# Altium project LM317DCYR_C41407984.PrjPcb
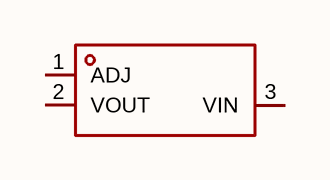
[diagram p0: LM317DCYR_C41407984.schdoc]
1 sheet, 1 parts. Net scope: global (net labels, ports and power ports of the same name join across sheets).

## Sheet LM317DCYR_C41407984.schdoc
size 127 x 101 mm

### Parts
U?  lm317dcyr_c41407984  [SOT-223-3_L6.5-W3.4-P2.30-LS7.0-BR-1]  (value not drawn)

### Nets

Not connected (* = marked no-connect by the designer): U? 1(ADJ) 2(VOUT) 3(VIN)

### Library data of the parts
U? = lm317dcyr_c41407984: 输出极性:正极;工作电压:40V;输出电压:1.2V~37V;输出电流:1.5A;电源纹波抑制比(PSRR):80dB@(120Hz);输出类型:可调;; Manufacturer: TECH PUBLIC(台舟); AddInBom: yes; ModelId: 0a360ebfdb9248a182f670f5fd8a68d2; ModelTransform: 275.59,255.905,0,0,0,0,-3.937,0,0; Output Configuration: 正极; Voltage - Supply: 40V; Output Current: 1.5A; Noise: 0.003%Vout; Output Type: 可调; Number of Outputs: 1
